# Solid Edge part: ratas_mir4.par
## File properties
Author: Kalle
Template: Iso Part.par
Last saved by: Kalle
Revision: 2
Application: Solid Edge
Accuracy: 0,990
Username: Kalle
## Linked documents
ratas.par
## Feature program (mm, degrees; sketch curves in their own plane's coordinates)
part copy "CopiedPart_1"
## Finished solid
Body 1: solid body, 6 faces, 6 edges, 0 vertices.
  Faces by surface: cylinder 3, plane 3
  Edges by curve: circle 6
Bounding box of the edges (mm): 30.000 x 12.000 x 30.000, from (13.8781, 0, -41.601) to (43.8781, 12, -11.601).
Cylindrical faces by radius (mm): R4 x1, R10 x1, R15 x1
Planar faces by outward normal: +y 2, -y 1
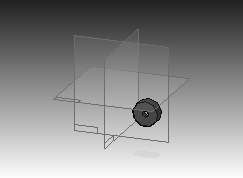
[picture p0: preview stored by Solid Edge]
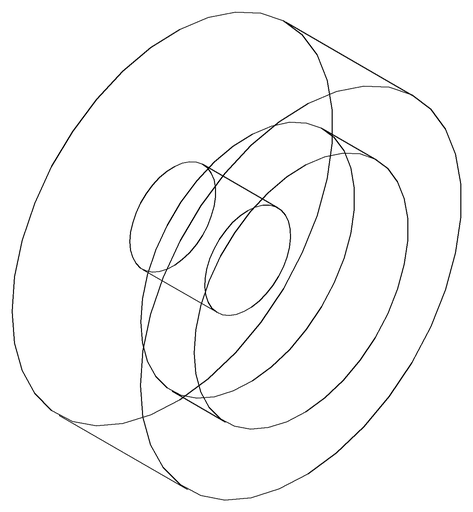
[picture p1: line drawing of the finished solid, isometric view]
